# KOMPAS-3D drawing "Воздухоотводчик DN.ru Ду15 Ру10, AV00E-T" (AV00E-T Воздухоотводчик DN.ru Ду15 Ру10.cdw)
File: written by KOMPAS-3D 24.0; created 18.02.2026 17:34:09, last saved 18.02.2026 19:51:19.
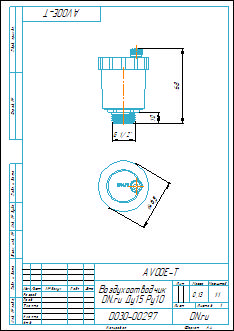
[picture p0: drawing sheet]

Document properties: Автор: R2D2; Форматы листов документа: A4; Полное имя файла: AV00E-T Воздухоотводчик DN.ru.m3d; Масса: 0.13; Наименование: Воздухоотводчик DN.ru Ду15 Ру10; Количество листов документа: 1; Примечание: D030-00297

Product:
- Part/product: Воздухоотводчик DN.ru Ду15 Ру10  | designation AV00E-T
    Масса: 0.13
    Раздел спецификации: Прочие изделия
    Примечание: D030-00297

Views: Вид 1, Справа, Проекционный вид 2
Referenced files in E:\Работа\Зайцев\Солянка\AV00E-T Воздухоотводчик DN.ru\Ду15 Ру10\: AV00E-T Воздухоотводчик DN.ru.m3d
Referenced files in E:\Работа\Зайцев\Для компаса\: чертеж DN.ru.cdt
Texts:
  Линейный размер
  AV00E-T
  чертеж DN.ru.cdt
  Воздухоотводчик
  DN.ru Ду15 Ру10
  Воздухоотводчик DN.ru Ду15 Ру10
  AV00E-T Воздухоотводчик DN.ru Ду15 Ру10
Dimensions and other numbers on the sheet: 0; 3; 2; 4; 68; 10; 46,5; 1:1; 1; 0,13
